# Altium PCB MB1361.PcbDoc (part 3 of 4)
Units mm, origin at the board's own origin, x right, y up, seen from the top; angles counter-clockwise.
Board outline 70 x 133.34 mm, 6 copper layers (Top Layer, Signal Layer 1, Signal Layer 2, Signal Layer 3, Signal Layer 4, Bottom Layer), stack 1.578 mm thick; 268 components, 251 nets, 1066 pads, 705 vias.
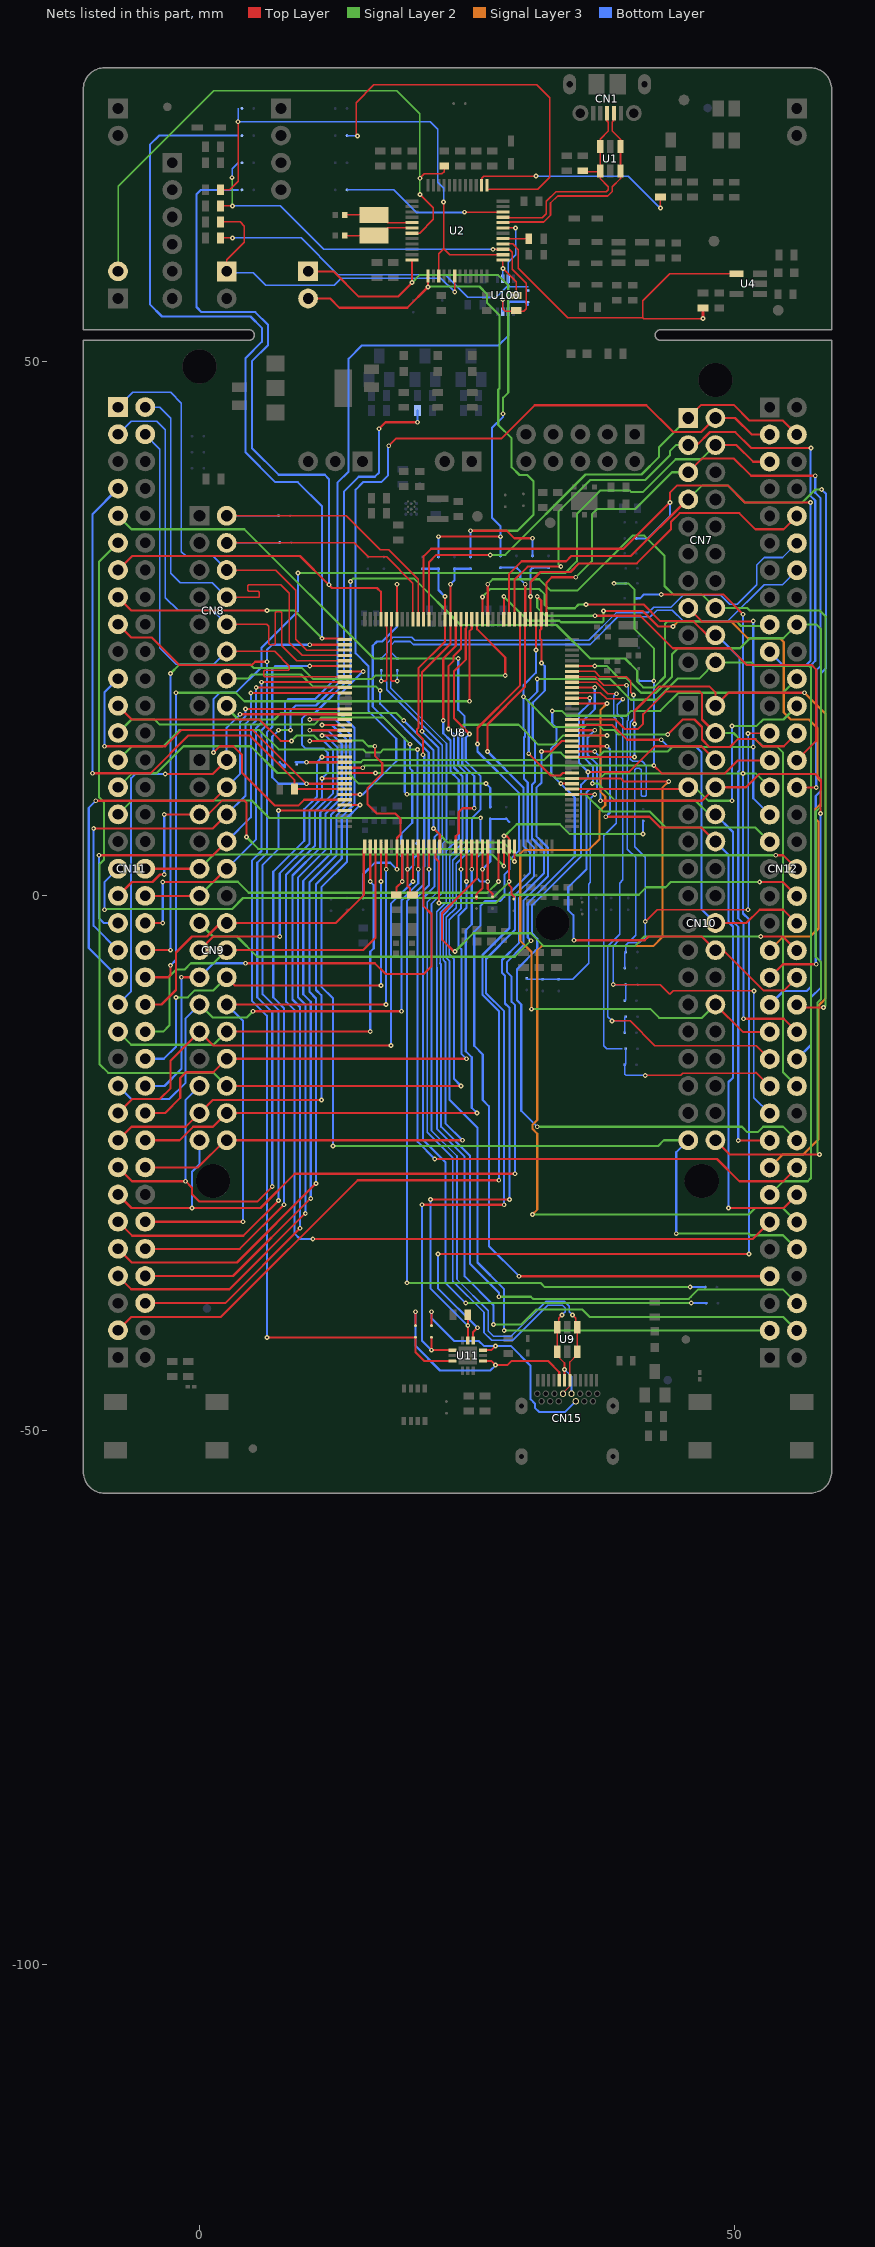
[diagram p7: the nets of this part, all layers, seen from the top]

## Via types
v1: diameter 0.45, hole 0.2, Top Layer to Bottom Layer, tented both sides, 705 vias

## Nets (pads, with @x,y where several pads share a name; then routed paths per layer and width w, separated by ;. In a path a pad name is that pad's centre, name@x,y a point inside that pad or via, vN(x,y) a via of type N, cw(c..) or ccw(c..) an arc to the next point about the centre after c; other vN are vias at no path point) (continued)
PA10: CN12.33 U8.102 | length 61.1
  Top Layer w0.2: U8.102@18.467,26.065 v1(18.467,29.147)
  Signal Layer 2 w0.2: v1(19.4,9.5) 36.1,9.5 37.7,7.9 42.1,7.9 43.605,6.395 52,6.395 CN12.33@53.34,5.055
  Bottom Layer w0.2: v1(18.467,29.147) 18.467,25.167 17.1,23.8 16.6,23.8 16.2,23.4 16.2,17.7 19.2,14.7 19.2,9.7 v1(19.4,9.5)
PA11: CN12.14 SB137.1 | length 43.4
  Bottom Layer w0.155: SB137.1@18.5,22.2 17.941,22.759 17.941,23.5 18.24,23.8 19.7,23.8 19.981,23.519 36.558,23.519 39.139,26.1 42.17,26.1 42.8,26.73 44.214,26.73 45.222,25.722 49.446,25.722 52.842,29.117 54.542,29.117 CN12.14@55.88,30.455
PA12: CN12.12 SB138.1 | length 45.9
  Bottom Layer w0.155: SB138.1@17,22.2 17.56,22.759 17.56,23.658 18.083,24.181 19.858,24.181 20.139,23.9 36.4,23.9 39,26.5 41.988,26.5 42.5,27.012 44.107,27.012 45.222,28.126 48.758,28.126 49.604,27.281 50.318,27.281 52.138,29.101 52.138,30.953 52.842,31.657 54.542,31.657 CN12.12@55.88,32.995
PA13: CN11.13 SB107.1 U8.105 | length 81.3
  Top Layer w0.2: CN11.13@-7.62,30.48 -6.305,31.795 9.405,31.795 v1(12.1,29.1) 12.4,28.8 16.61,28.8 16.967,28.443 U8.105@16.967,26.09
  Bottom Layer w0.2: 3.613,66.04 0.14,66.04 -0.279,65.621 -0.279,55.079 0.191,54.609 5.22,54.609 6.4,53.429 6.4,51.5 4.9,50 4.9,41.9 7.41,39.39 11.71,39.39 12.1,39 v1(12.1,29.1)
PA14: CN11.15 SB103.1 U8.109 | length 91.4
  Top Layer w0.2: CN11.15@-7.62,27.94 -6.38,26.7 v1(6.3,26.7) ; v1(11.465,24.09) U8.109@13.367,24.09
  Signal Layer 2 w0.2: v1(6.3,26.7) 8.855,26.7 v1(11.465,24.09)
  Bottom Layer w0.2: 3.613,71.12 -3.785,71.12 -4.648,70.256 -4.648,55.347 -3.502,54.2 4.763,54.2 5.831,53.132 5.831,51.831 4.3,50.3 4.3,41.5 7.1,38.7 9.2,38.7 11.465,36.435 v1(11.465,24.09)
PA15: CN11.17 SB10.1 U8.110 U11.3 | length 107.5
  Top Layer w0.2: CN11.17@-7.62,25.4 -6.395,24.175 -4.475,24.175 -1.9,21.6 4.9,21.6 5.2,21.9 v1(6.3,21.9) ; v1(6.3,-41.3) SB10.1@20.2,-41.3 20.2,-42.7 21,-43.5 U11.3@23.675,-43.5 ; v1(10.31,23.49) U8.110@13.392,23.49
  Bottom Layer w0.2: v1(6.3,-41.3) 6.3,-11.2 4.9,-9.8 4.9,3.3 5.8,4.2 5.8,15.5 6.3,16 v1(6.3,21.9) 6.3,23 6.79,23.49 v1(10.31,23.49)
PB0: SB160.1 SB161.1 SB162.2 U8.43 | length 24.4
  Top Layer w0.127: U8.43@35.067,9.49 v1(36.969,9.49)
  Bottom Layer w0.127: SB162.2@30.6,-7.7 30.7,-7.8 SB161.1@32.1,-7.8 SB160.1@33.6,-7.8 34.9,-7.8 36.4,-6.3 36.4,1.102 36.553,1.255 36.553,9.074 v1(36.969,9.49)
PB1: CN10.7 CN12.24 U8.44 | length 29.2
  Top Layer w0.2: U8.44@35.042,9.99 45.55,9.99 CN10.7@45.72,10.16
  Signal Layer 2 w0.2: CN10.7@45.72,10.16 46.34,10.16 47.6,8.9 v1(49.8,8.9) ; v1(49.8,15.9) 52.12,15.9 52.72,16.5 54.625,16.5 CN12.24@55.88,17.755
  Bottom Layer w0.2: v1(49.8,8.9) v1(49.8,15.9)
PB2: CN9.13 CN12.22 U8.45 | length 83.4
  Top Layer w0.2: v1(33.8,10.5) 35.057,10.5 U8.45@35.067,10.49
  Signal Layer 2 w0.2: CN9.13@0,-2.54 1.26,-3.8 3.5,-3.8 5.4,-5.7 29.5,-5.7 v1(31,-4.2) ; v1(33,17.3) 33.9,17.3 34.352,16.848 39.948,16.848 40.4,17.3 43.1,17.3 44.805,19.005 54.59,19.005 CN12.22@55.88,20.295
  Bottom Layer w0.2: v1(31,-4.2) 30.7,-3.9 30.7,-0.7 35.1,3.7 35.1,9.2 v1(33.8,10.5) 32.9,11.4 32.9,13.8 33.4,14.3 33.4,15.7 33.009,16.091 33,16.081 v1(33,17.3)
PB3: CN7.15 CN12.31 SB140.2 U8.132 | length 72.6
  Top Layer w0.2: v1(10,12.5) 13.382,12.5 U8.132@13.392,12.49 ; CN7.15@45.72,26.924 46.97,25.674 51.774,25.674 v1(51.8,25.7)
  Signal Layer 2 w0.2: v1(10,12.5) 15.08,12.5 15.28,12.7 32.2,12.7 32.9,13.4 33.8,13.4 34.3,12.9 37.2,12.9 37.8,13.5 43.8,13.5 44.225,13.925 v1(51.8,13.925)
  Bottom Layer w0.2: 8.99,12.49 9,12.5 v1(10,12.5) ; v1(51.8,25.7) v1(51.8,13.925) 51.8,9.135 CN12.31@53.34,7.595
PB4: CN12.27 SB134.1 SB139.1 U8.133 | length 62.8
  Top Layer w0.2: U8.133@13.392,11.99 v1(15.269,11.99) ; v1(42.5,12.2) 43.244,11.456 49.156,11.456 50.375,12.675 CN12.27@53.34,12.675
  Signal Layer 2 w0.2: v1(15.269,11.99) 15.479,12.2 v1(42.5,12.2) ; v1(38.767,29.236) 40.11,29.236 40.7,28.646 40.7,24.95 42.5,23.15 v1(42.5,20.1)
  Bottom Layer w0.127: CN12.27@53.34,12.675 CN12.27@53.34,12.725
  Bottom Layer w0.2: v1(38.767,29.236) SB134.1@39.867,29.236 ; SB139.1@41.1,20.1 v1(42.5,20.1) v1(42.5,12.2)
PB5: CN12.29 SB135.1 U8.134 U11.10 | length 150.7
  Top Layer w0.2: U8.134@13.392,11.49 U8.134@13.592,11.49 v1(16.474,11.49) ; v1(22.3,-33.5) v1(51.4,-33.5) ; U11.10@25.6,-41.575 25.6,-40.8 v1(26,-40.4) ; v1(43.2,28.2) 48.996,28.2 v1(50.848,26.348)
  Signal Layer 2 w0.2: v1(16.474,11.49) 32.81,11.49 33.31,10.99 37.485,10.99 37.951,11.456 v1(50.848,11.456) 52.019,11.456 CN12.29@53.34,10.135
  Bottom Layer w0.2: v1(22.3,-33.5) 22.3,-36.7 v1(26,-40.4) ; SB135.1@40.867,27.836 41.213,27.836 41.577,28.2 v1(43.2,28.2) ; v1(50.848,26.348) v1(50.848,11.456) 50.848,-1.648 51.4,-2.2 v1(51.4,-33.5)
PB6: CN9.15 CN12.17 U8.135 | length 99.2
  Top Layer w0.2: CN9.15@0,-5.08 1.28,-3.8 v1(7.5,-3.8) ; v1(11.465,10.99) U8.135@13.367,10.99
  Signal Layer 2 w0.2: v1(14.117,29.417) 14.4,29.7 20.05,29.7 24.41,25.34 33.4,25.34 36.54,22.2 39.8,22.2 40.95,21.05 40.95,20.05 41.5,19.5 42.539,19.5 43.552,20.513 43.552,25.452 43.774,25.674 50.226,25.674 50.652,25.248 53.34,25.248 CN12.17@53.34,25.375
  Bottom Layer w0.2: v1(7.5,-3.8) 7.5,2.1 10.3,4.9 10.3,8 11.465,9.165 v1(11.465,10.99) 12,11.525 12,13.4 11.6,13.8 9.9,13.8 9.6,14.1 9.6,16.6 10.1,17.1 10.8,17.1 14.117,20.417 v1(14.117,29.417)
PB7: CN11.21 R107.1 U8.136 | length 79.6
  Top Layer w0.2: v1(-8.89,14) -3.2,14 -1.7,15.5 4.99,15.5 v1(10,10.49) U8.136@13.392,10.49 ; v1(16.79,43.69) 17.4,44.3 v1(20.4,44.3)
  Signal Layer 2 w0.2: v1(7.4,15.5) v1(8.5,15.5)
  Bottom Layer w0.2: v1(-8.89,14) -8.89,19.05 CN11.21@-7.62,20.32 ; v1(7.4,15.5) 6.8,14.9 6.8,11.1 7.41,10.49 v1(10,10.49) ; v1(8.5,15.5) 8.5,17.3 9,17.8 10.9,17.8 13.5,20.4 13.5,37.8 14.9,39.2 16.4,39.2 16.79,39.59 v1(16.79,43.69) ; v1(20.4,44.3) R107.1@20.4,45.4
PB8: CN7.2 CN12.3 U8.138 | length 79.1
  Top Layer w0.2: U8.138@13.392,9.49 U8.138@13.592,9.49 v1(15,9.49) ; v1(17.7,42.1) 18.4,42.8 28.265,42.8 31.365,45.9 41.8,45.9 44.3,43.4 46.956,43.4 CN7.2@48.26,44.704 50.096,44.704 51.645,43.155 CN12.3@53.34,43.155
  Bottom Layer w0.2: v1(15,9.49) 15.294,9.49 18.4,12.596 18.4,14.7 15.8,17.3 15.8,21.5 14.6,22.7 14.6,38 15.3,38.7 17,38.7 17.648,39.348 17.648,42.048 v1(17.7,42.1)
PB9: CN7.4 CN12.5 U8.139 | length 89.2
  Top Layer w0.2: v1(1.3,13.4) 1.9,14 3.16,14 3.97,13.19 3.97,11.53 7.058,8.442 9.242,8.442 9.79,8.99 U8.139@13.367,8.99 ; CN7.4@48.26,42.164 50.236,42.164 51.785,40.615 CN12.5@53.34,40.615
  Signal Layer 2 w0.2: v1(9.2,30.2) 34.2,30.2 35.3,31.3 35.3,35.723 37.512,37.935 40.231,37.935 40.402,37.764 41.464,37.764 44.549,40.849 46.945,40.849 CN7.4@48.26,42.164
  Bottom Layer w0.2: v1(1.3,13.4) 1.3,18.405 1.9,19.005 3.405,19.005 5.8,21.4 5.8,23.2 9.2,26.6 v1(9.2,30.2)
PB10: CN12.25 SB151.1 SB157.2 U8.66 | length 70.5
  Top Layer w0.127: U8.66@35.042,20.99 36.969,20.99 37.459,20.5 39.9,20.5 40.347,20.053 40.347,19.053 v1(40.6,18.8) ; v1(41.7,-2.4) 42.8,-1.3 v1(51.3,-1.3) ; v1(51.3,15.2) 53.325,15.2 CN12.25@53.34,15.215
  Bottom Layer w0.127: SB157.2@39.775,-6.75 39.775,-5.35 SB151.1@39.875,-5.25 39.875,-4.625 40.1,-4.4 41.152,-4.4 41.7,-3.852 v1(41.7,-2.4) 41.7,3.6 40.7,4.6 40.7,11.8 40.846,11.946 41.154,11.946 41.3,11.8 41.3,9.4 41.4,9.3 41.7,9.3 41.8,9.4 41.8,12.19 41.416,12.575 40.518,12.575 40.292,12.8 40.275,12.8 40.275,16.262 40.6,16.588 v1(40.6,18.8) ; v1(51.3,-1.3) 51.316,-1.284 51.316,15.184 v1(51.3,15.2)
PB11: CN10.34 CN12.18 U8.67 | length 88.3
  Top Layer w0.2: U8.67@35.067,21.49 v1(36.969,21.49) ; CN10.34@48.26,-22.86 49.6,-24.2 v1(58,-24.2)
  Signal Layer 2 w0.2: v1(36.969,21.49) 36.991,21.512 38.088,21.512 39.2,20.4 39.9,20.4 41.3,19 42.7,19 44.2,20.5 44.2,22.6 44.759,23.159 50.559,23.159 51.5,24.1 54.605,24.1 CN12.18@55.88,25.375 57.725,25.375 58.152,24.948 58.152,8.391 57.648,7.887 57.648,-5.709 58.152,-6.213 58.152,-9.648 57.8,-10 57.8,-24 v1(58,-24.2)
PB13: CN7.5 CN12.30 U8.74 | length 68.1
  Top Layer w0.127: CN12.30@55.88,10.135 CN12.30@56.051,10.135
  Top Layer w0.2: U8.74@32.467,26.065 32.467,29.317 32.95,29.8 v1(35.2,29.8) ; CN7.5@45.72,39.624 46.996,40.9 50,40.9 51.6,39.3 v1(57.6,39.3) ; CN12.30@55.88,10.135 v1(57.7,10.135)
  Signal Layer 2 w0.2: v1(35.2,29.8) 36.7,31.3 36.7,35.7 37.193,36.193 40.77,36.193 44.201,39.624 CN7.5@45.72,39.624
  Bottom Layer w0.127: CN12.30@55.88,10.135 CN12.30@56.051,10.135
  Bottom Layer w0.2: v1(57.6,39.3) 57.6,37.7 58.1,37.2 58.1,21.5 57.7,21.1 v1(57.7,10.135)
PB14: CN12.28 R43.1 U8.75 U11.11 | length 121.6
  Top Layer w0.2: v1(21.6,-28.4) v1(29,-28.4) ; U11.11@25.1,-41.575 v1(25.1,-40.2) R43.1@25.1,-39.2 ; v1(31.6,28) 31.967,27.633 U8.75@31.967,26.09 ; U8.75@31.967,26.065 U8.75@31.967,25.865 31.967,24.967 31.848,24.848 31.848,24.052 32,23.9 v1(32,21.792) ; v1(37,26.2) 41.239,26.2 44.28,23.159 49.641,23.159 51.2,21.6 57.26,21.6 57.7,21.16 57.7,14.495 CN12.28@55.88,12.675
  Signal Layer 2 w0.2: v1(31.6,28) 31.6,26.967 32.367,26.2 v1(37,26.2)
  Bottom Layer w0.2: v1(21.6,-28.4) 21.6,-36.7 v1(25.1,-40.2) ; v1(29,-28.4) 29,-10.48 28.584,-10.064 28.584,-7.484 28.3,-7.2 28.3,-6 29.9,-4.4 29.9,-0.2 32.228,2.128 32.228,4.239 31.1,5.367 31.1,10.4 31.4,10.7 31.4,14.439 31.167,14.672 31.167,18.067 32.3,19.2 32.3,21.492 v1(32,21.792)
PB15: CN12.26 SB11.1 U8.76 U11.1 | length 114
  Top Layer w0.2: v1(20.8,-28.9) v1(28.5,-28.9) ; SB11.1@21.7,-41.3 v1(21.7,-42.5) U11.1@23.675,-42.5 ; v1(31.467,23) U8.76@31.467,25.865 U8.76@31.467,26.065 ; v1(43.8,15.1) 45.2,16.5 46.3,16.5 47,15.8 47,14.625 47.7,13.925 49.625,13.925 50.358,14.658 51.992,14.658 52.66,13.99 54.655,13.99 CN12.26@55.88,15.215
  Signal Layer 2 w0.2: v1@30.3,18.642 v1(30.321,18.621) 33.142,15.8 36,15.8 36.2,16 37.3,16 37.8,15.5 38.8,15.5 39.2,15.1 v1(43.8,15.1)
  Bottom Layer w0.2: v1(20.8,-28.9) 20.8,-41.6 v1(21.7,-42.5) ; v1(28.5,-28.9) 28.5,-10.809 26.8,-9.109 26.8,-5.9 29.5,-3.2 29.5,0.05 31.3,1.85 31.3,4.5 30.7,5.1 30.7,10.6 30.348,10.952 30.348,14.809 30.452,14.913 30.452,15.5 30.321,15.631 v1(30.321,18.621) 30.321,19.721 31.467,20.867 v1(31.467,23)
PC0: CN9.11 CN11.38 U8.26 | length 37.5
  Top Layer w0.2: CN11.38@-5.08,0 CN9.11@0,0 ; v1(27.967,1.333) U8.26@27.967,4.415
  Signal Layer 2 w0.2: CN9.11@0,0 1.315,1.315 3.585,1.315 4.604,0.296 26.93,0.296 v1(27.967,1.333)
PC1: CN9.9 CN11.36 U8.27 | length 36.1
  Top Layer w0.2: CN11.36@-5.08,2.54 CN9.9@0,2.54 ; v1(28.467,2.8) U8.27@28.467,4.39
  Signal Layer 2 w0.2: CN9.9@0,2.54 1.315,3.855 27.412,3.855 v1(28.467,2.8)
PC2: CN11.35 SB8.1 SB144.1 U8.28 | length 64.6
  Top Layer w0.2: v1(28.483,5.6) 28.711,5.6 28.967,5.344 U8.28@28.967,4.615 v1(28.967,1.333) 28.967,1.006 29.2,0.773 29.2,0.151 29.451,-0.1
  Signal Layer 2 w0.2: v1(-8.9,-1.3) -8.825,-1.225 3.047,-1.225 4.072,-0.2 27.434,-0.2 v1(28.967,1.333) ; v1(28.483,5.6) 28.567,5.6 29.667,6.7 33.7,6.7 34.6,5.8 v1(41.5,5.8)
  Bottom Layer w0.2: v1(-8.9,-1.3) -8.9,1.26 CN11.35@-7.62,2.54 ; v1(41.5,5.8) SB144.1@41.5,7
PC3: CN9.5 CN11.37 U8.29 | length 49.5
  Top Layer w0.2: CN11.37@-7.62,0 -6.32,1.3 -4.4,1.3 -3.7,2 v1(-3.3,2) ; v1(-3.3,7.62) CN9.5@0,7.62 0.808,7.62 2.123,8.935 4.165,8.935 4.4,8.7 v1(4.4,5.5) ; v1(29.467,3.2) U8.29@29.467,4.39
  Signal Layer 2 w0.2: v1(4.4,5.5) 5.5,4.4 28.267,4.4 v1(29.467,3.2)
  Bottom Layer w0.2: v1(-3.3,2) v1(-3.3,7.62)
PC6: CN7.1 CN12.4 U8.96 | length 47.3
  Top Layer w0.2: U8.96@21.467,26.065 21.467,31.217 22.15,31.9 v1(27.2,31.9) ; CN7.1@45.72,44.704 46.945,45.929 49.971,45.929 51.43,44.47 54.565,44.47 CN12.4@55.88,43.155
  Signal Layer 2 w0.2: v1(27.2,31.9) 28.6,31.9 36.115,39.415 41.353,39.415 43,41.062 43,41.984 CN7.1@45.72,44.704
PC7: CN12.19 SB118.1 U8.97 | length 70.4
  Top Layer w0.2: U8.97@20.967,26.09 20.967,31.767 21.667,32.467 39.667,32.467 v1(44,36.8) 44,37.71 44.689,38.399 46.227,38.399 46.228,38.4 47.752,38.4 47.753,38.399 49.401,38.399 51,36.8 v1(57.15,36.8)
  Bottom Layer w0.2: SB118.1@40.867,33.436 41.936,33.436 44,35.5 v1(44,36.8) ; CN12.19@53.34,22.835 54.575,21.6 56.76,21.6 57.15,21.99 v1(57.15,36.8)
PC8: CN8.2 SB119.2 U8.98 | length 28.8
  Top Layer w0.127: CN8.2@2.54,35.56 13.74,35.56 16.925,32.375 17.725,32.375 20.467,29.633 U8.98@20.467,26.065
  Bottom Layer w0.127: CN8.2@2.54,35.56 SB119.2@7.4,35.56
PC9: CN8.4 SB122.1 U8.99 | length 27.2
  Top Layer w0.127: CN8.4@2.54,33.02 14.48,33.02 15.8,31.7 17.518,31.7 19.967,29.251 U8.99@19.967,26.065
  Bottom Layer w0.127: CN8.4@2.54,33.02 7.46,33.02 SB122.1@7.5,33.06
PC10: CN8.6 CN11.1 U8.111 | length 42.4
  Top Layer w0.127: CN8.6@2.54,30.48 7.12,30.48 9,28.6 9,24.02 10.03,22.99 U8.111@13.392,22.99
  Bottom Layer w0.127: CN11.1@-7.62,45.72 -6.24,47.1 -2.7,47.1 -1.7,46.1 -1.7,32.2 -1.3,31.8 1.22,31.8 CN8.6@2.54,30.48
PC11: CN8.8 CN11.2 U8.112 | length 42.9
  Top Layer w0.127: CN8.8@2.54,27.94 5.54,27.94 5.6,28 5.6,28.4 5.5,28.5 4.6,28.5 4.5,28.6 4.5,29 4.6,29.1 7.6,29.1 8.4,28.3 8.4,23.7 9.61,22.49 U8.112@13.392,22.49
  Bottom Layer w0.127: CN11.2@-5.08,45.72 -3.72,45.72 -2.7,44.7 -2.7,30.2 -1.78,29.28 1.2,29.28 CN8.8@2.54,27.94
PC12: CN8.10 CN11.3 U8.113 | length 47
  Top Layer w0.127: CN8.10@2.54,25.4 6.3,25.4 6.5,25.2 6.5,23.6 6.6,23.5 7,23.5 7.1,23.6 7.1,26.5 7.2,26.6 7.6,26.6 7.7,26.5 7.7,23.4 9.11,21.99 U8.113@13.392,21.99
  Bottom Layer w0.127: CN11.3@-7.62,43.18 -6.4,44.4 -4.01,44.4 -3.2,43.59 -3.2,27.9 -2,26.7 1.24,26.7 CN8.10@2.54,25.4
PC13: CN11.23 SB154.2 U8.7 | length 46.9
  Top Layer w0.2: CN11.23@-7.62,17.78 -6.34,16.5 5.6,16.5 7.6,14.5 v1(8.6,14.5) ; v1(16.4,14) 16.4,13.1 17.1,12.4 17.1,11.477 15.7,10.077 15.7,8.587 16.587,7.7 18.3,7.7 18.8,7.2 18.8,5.75 18.467,5.417 U8.7@18.467,4.615 U8.7@18.467,4.415 ; v1(18.467,2.488) U8.7@18.467,4.39
  Signal Layer 2 w0.2: v1(8.6,14.5) 9.1,15 10.7,15 11.162,14.538 15.262,14.538 15.8,14 v1(16.4,14)
  Bottom Layer w0.2: SB154.2@15.3,-0.2 15.3,2 16.4,3.1 17.855,3.1 v1(18.467,2.488)
PC14: CN11.25 SB148.2 | length 39.2
  Signal Layer 2 w0.2: CN11.25@-7.62,15.24 -6.36,16.5 -4.2,16.5 -3.72,16.02 10.72,16.02 11.4,16.7 17.19,16.7 v1(19.7,14.19)
  Bottom Layer w0.2: SB148.2@18.867,4.9 18.867,5.8 19.9,6.833 19.9,11.7 19.7,11.9 v1(19.7,14.19)
PC14-OSC32_IN: R34.1 SB148.1 U8.8 | length 7.1
  Top Layer w0.2: R34.1@18.417,0.096 18.417,0.783 v1(18.967,1.333) U8.8@18.967,4.415
  Bottom Layer w0.2: SB148.1@18.867,3.8 18.967,3.7 v1(18.967,1.333)
PC15: CN11.27 SB147.2 | length 39
  Signal Layer 2 w0.2: CN11.27@-7.62,12.7 -6.32,14 -3.4,14 -1.9,15.5 5.6,15.5 7.4,13.7 15.3,13.7 15.6,13.4 16.9,13.4 17.2,13.7 v1(20.4,13.7)
  Bottom Layer w0.2: SB147.2@20.3,4.9 20.4,5 v1(20.4,13.7)
PC15-OSC32_OUT: R35.1 SB147.1 U8.9 | length 6.2
  Top Layer w0.2: U8.9@19.467,4.39 v1(19.467,2.488) 19.467,0.923 19.7,0.69 19.7,0.305 R35.1@19.916,0.089
  Bottom Layer w0.2: v1(19.467,2.488) 19.623,2.488 20,2.865 20,3.5 SB147.1@20.3,3.8
PD0: CN9.25 CN11.57 U8.114 | length 82.4
  Top Layer w0.2: CN11.57@-7.62,-25.4 -6.32,-26.7 v1(-1.3,-26.7) -0.7,-27.3 -0.7,-27.9 0,-28.6 5.4,-28.6 v1(6.8,-27.2) ; v1(10.31,21.49) U8.114@13.392,21.49
  Bottom Layer w0.2: v1(-1.3,-26.7) -1.3,-19.08 CN9.25@0,-17.78 ; v1(6.8,-27.2) 6.8,-10.9 5.4,-9.5 5.4,3.1 6.3,4 6.3,15.3 6.8,15.8 6.8,21.2 7.09,21.49 v1(10.31,21.49)
PD1: CN9.27 CN11.55 U8.115 | length 65.9
  Top Layer w0.2: CN11.55@-7.62,-22.86 -6.36,-21.6 -1.28,-21.6 CN9.27@0,-20.32 1.225,-19.095 v1(11.4,-19.095) ; U8.115@13.417,20.99 v1(15.319,20.99)
  Bottom Layer w0.2: v1(11.4,-19.095) 11.4,-9.3 10.9,-8.8 10.9,1.1 13.3,3.5 13.3,7.4 14.5,8.6 14.5,15.7 13,17.2 13,18.706 15.284,20.99 v1(15.319,20.99)
PD2: CN8.12 CN11.4 U8.116 | length 45
  Top Layer w0.127: CN8.12@2.54,22.86 7.04,22.86 8.4,21.5 8.4,21.2 8.3,21.1 6.1,21.1 6,21 6,20.6 6.11,20.49 U8.116@13.392,20.49
  Bottom Layer w0.127: CN11.4@-5.08,43.18 -3.7,41.8 -3.7,23.2 -2.16,21.66 1.34,21.66 CN8.12@2.54,22.86
PD3: CN9.10 CN11.40 U8.117 | length 38.3
  Top Layer w0.2: CN11.40@-5.08,-2.54 v1(-3.44,-2.54) ; v1(-3.44,1.3) 1.3,1.3 CN9.10@2.54,2.54 ; v1(5.8,19.99) U8.117@13.367,19.99
  Bottom Layer w0.2: v1(-3.44,-2.54) v1(-3.44,1.3) ; CN9.10@2.54,2.54 5.3,5.3 5.3,15.7 5.8,16.2 v1(5.8,19.99)
PD4: CN9.8 CN11.39 U8.118 | length 44
  Top Layer w0.2: v1(-9.4,3.8) 1.26,3.8 CN9.8@2.54,5.08 ; v1(5.3,19.49) U8.118@13.392,19.49
  Bottom Layer w0.2: v1(-9.4,3.8) -9.4,-2.1 -8.96,-2.54 CN11.39@-7.62,-2.54 ; CN9.8@2.54,5.08 4.8,7.34 4.8,15.9 5.3,16.4 v1(5.3,19.49)
PD5: CN9.6 CN11.41 U8.119 | length 46.2
  Top Layer w0.2: v1(-9.9,6.305) 1.225,6.305 CN9.6@2.54,7.62 ; v1(4.8,18.99) U8.119@13.367,18.99
  Bottom Layer w0.2: v1(-9.9,6.305) -9.9,-2.8 CN11.41@-7.62,-5.08 ; CN9.6@2.54,7.62 4.31,9.39 4.31,16.11 4.8,16.6 v1(4.8,18.99)
PD6: CN9.4 CN11.43 U8.122 | length 47.8
  Top Layer w0.2: v1(-9.7,8.9) 1.28,8.9 CN9.4@2.54,10.16 ; v1(4.3,17.49) U8.122@13.392,17.49
  Bottom Layer w0.2: v1(-9.7,8.9) -10.366,8.234 -10.366,-4.874 CN11.43@-7.62,-7.62 ; CN9.4@2.54,10.16 3.8,11.42 3.8,16.3 4.3,16.8 v1(4.3,17.49)
PD7: CN9.2 CN11.45 U8.123 | length 45.7
  Top Layer w0.2: v1(-3.2,11.4) 1.24,11.4 CN9.2@2.54,12.7 ; v1(3.8,16.99) U8.123@13.367,16.99
  Bottom Layer w0.2: CN11.45@-7.62,-10.16 -6.395,-8.935 -6.395,11.005 -6,11.4 v1(-3.2,11.4) ; CN9.2@2.54,12.7 2.54,15.73 v1(3.8,16.99)
PD8: CN12.10 SB123.1 SB124.1 U8.77 | length 36.7
  Top Layer w0.2: U8.77@30.967,26.09 v1(30.967,27.992) 30.967,29.367 31.9,30.3 34.7,30.3 35.5,31.1 40.9,31.1 44.1,34.3 44.1,34.985 44.915,35.8 50.5,35.8 52,34.3 54.645,34.3 CN12.10@55.88,35.535
  Bottom Layer w0.2: v1(30.967,27.992) 30.967,30.517 SB124.1@31.15,30.7 SB123.1@32.65,30.7
PD9: CN11.69 SB125.1 SB126.1 U8.78 | length 106.2
  Top Layer w0.2: CN11.69@-7.62,-40.64 -6.38,-39.4 2,-39.4 14.8,-26.6 v1(28,-26.6) ; v1(26.936,13.5) 26.936,16.036 30.448,19.548 30.448,26.046 30.467,26.065 v1(30.467,29.147)
  Bottom Layer w0.2: v1(26.936,13.5) 30.3,10.136 30.3,4.7 30.919,4.081 30.919,2.163 29,0.244 29,-3.008 26.473,-5.535 26.473,-9.244 28,-10.771 v1(28,-26.6) ; SB126.1@28.15,30.7 SB125.1@29.65,30.7 30,30.35 30,29.614 v1(30.467,29.147)
PD10: CN12.65 U8.79 | length 92.6
  Top Layer w0.2: v1(26,14.2) 26,15.7 29.967,19.667 U8.79@29.967,25.865 U8.79@29.967,26.065 ; v1(29.9,-35.585) CN12.65@53.34,-35.585
  Bottom Layer w0.2: v1(26,14.2) 26,13.5 29.9,9.6 29.9,4.272 29.015,3.387 29.015,2.49 28.515,1.99 28.515,-0.085 28.114,-0.486 26.724,-0.486 26.3,-0.91 26.3,-2.75 25.7,-3.35 25.7,-14.036 26.5,-14.836 26.5,-19.1 27.069,-19.669 27.069,-32.754 v1(29.9,-35.585)
PD11: CN7.3 CN12.45 U8.80 | length 96.5
  Top Layer w0.2: U8.80@29.467,26.065 29.467,29.567 30.7,30.8 v1(33.8,30.8) ; CN7.3@45.72,42.164 46.528,42.164 47.753,43.389 49.476,43.389 49.485,43.38 50.12,43.38 51.6,41.9 v1(57.2,41.9)
  Signal Layer 2 w0.2: v1(33.8,30.8) 33.569,31.031 33.569,35.919 36.55,38.9 41.7,38.9 44,41.2 44,41.6 44.564,42.164 CN7.3@45.72,42.164
  Bottom Layer w0.2: CN12.45@53.34,-10.185 54.625,-8.9 56.8,-8.9 57.2,-8.5 57.2,21.578 57.602,21.98 57.602,36.987 57.148,37.441 57.148,41.848 v1(57.2,41.9)
PD12: CN7.7 CN12.43 U8.81 | length 87.7
  Top Layer w0.2: U8.81@28.967,26.09 28.967,30.117 30.15,31.3 34.3,31.3 34.8,31.8 40.361,31.8 45.645,37.084 CN7.7@45.72,37.084 ; CN12.43@53.34,-7.645 54.585,-6.4 v1(57.7,-6.4)
  Signal Layer 2 w0.2: CN7.7@45.72,37.084 47.035,38.399 49.401,38.399 51,36.8 56.378,36.8 57.578,38 v1(58.2,38)
  Bottom Layer w0.2: v1(57.7,-6.4) 57.648,-6.348 57.648,9.348 58.152,9.852 58.152,20.852 58.6,21.3 58.6,37.6 v1(58.2,38)
PD13: CN12.41 U8.82 | length 66.7
  Top Layer w0.2: U8.82@28.467,26.065 v1(28.467,28) ; v1(37.8,26.652) 41.448,26.652 42.9,25.2 v1(44.3,25.2)
  Signal Layer 2 w0.2: v1(28.467,28) 30.727,25.74 33.66,25.74 33.8,25.6 37.7,25.6 37.8,25.7 v1(37.8,26.652)
  Signal Layer 3 w0.2: v1(44.3,25.2) 44.774,25.674 49.726,25.674 51.3,24.1 54.3,24.1 54.655,23.745 54.655,17.145 55.3,16.5 57,16.5 57.8,15.7 57.8,11 58.152,10.648 58.152,8.652 57.648,8.148 57.648,7.2 57.9,6.948 57.9,-3.048 57.158,-3.79 54.655,-3.79 CN12.41@53.34,-5.105
PD14: CN7.16 CN12.46 U8.85 | length 81.5
  Top Layer w0.2: U8.85@26.967,26.065 v1(26.967,29.147) ; CN12.46@55.88,-10.185 56.142,-10.447 v1(58.358,-10.447)
  Signal Layer 2 w0.2: v1(26.967,29.147) 27.434,29.614 31.786,29.614 32.848,28.552 35.352,28.552 40.5,33.7 41.6,33.7 43.5,31.8 43.5,28.99 44.29,28.2 46.984,28.2 CN7.16@48.26,26.924 51.224,26.924 51.458,26.69 58.01,26.69 58.6,26.1 58.552,26.052 58.552,-10.253 v1(58.358,-10.447)
PD15: CN7.18 CN12.48 U8.86 | length 69.3
  Top Layer w0.2: U8.86@26.467,26.065 v1(26.467,27.967) ; v1(36.152,27.248) 41.552,27.248 43.101,25.699 46.201,25.699 47.516,24.384 CN7.18@48.26,24.384 ; v1(50.9,-11.5) 54.655,-11.5 CN12.48@55.88,-12.725
  Signal Layer 2 w0.2: v1(26.467,27.967) 27.195,28.695 31.805,28.695 32.3,28.2 32.3,27.215 32.615,26.9 35.1,26.9 35.448,27.248 v1(36.152,27.248)
  Bottom Layer w0.2: CN7.18@48.26,24.384 48.416,24.384 50.5,22.3 50.5,11.747 50.396,11.643 50.396,-2.096 50.9,-2.6 v1(50.9,-11.5)
PE0: CN10.33 CN12.64 U8.140 | length 90
  Top Layer w0.2: U8.140@13.392,8.49 U8.140@13.592,8.49 v1(15,8.49)
  Signal Layer 2 w0.2: v1(12.5,-23.4) 42.9,-23.4 43.44,-22.86 CN10.33@45.72,-22.86 ; v1(44.6,-31.6) 51.4,-31.6 51.545,-31.745 54.58,-31.745 CN12.64@55.88,-33.045
  Bottom Layer w0.2: v1(12.5,-23.4) 12.5,-9.6 11.4,-8.5 11.4,0.8 13.8,3.2 13.8,7.29 v1(15,8.49) ; v1(44.6,-31.6) 44.6,-23.98 CN10.33@45.72,-22.86
PE1: CN11.61 U8.141 | length 60.7
  Top Layer w0.2: CN11.61@-7.62,-30.48 -6.305,-31.795 4.105,-31.795 v1(7.4,-28.5) ; v1(7.4,7.99) U8.141@13.392,7.99
  Bottom Layer w0.2: v1(7.4,-28.5) 7.4,-10.7 5.9,-9.2 5.9,2.9 7.4,4.4 v1(7.4,7.99)
PE2: CN9.14 CN11.46 U8.1 | length 31.1
  Top Layer w0.2: CN11.46@-5.08,-10.16 -3.56,-10.16 -2.2,-8.8 -2.2,-5.3 -0.7,-3.8 0.7,-3.8 1.96,-2.54 CN9.14@2.54,-2.54 12.76,-2.54 15.367,0.067 U8.1@15.367,4.39
PE3: CN9.22 CN11.47 U8.2 | length 42
  Top Layer w0.2: CN9.22@2.54,-12.7 v1(15.967,-12.7) ; v1(15.967,1.333) U8.2@15.967,4.415
  Signal Layer 2 w0.2: CN11.47@-7.62,-12.7 -6.395,-13.925 1.315,-13.925 CN9.22@2.54,-12.7
  Bottom Layer w0.2: v1(15.967,-12.7) 15.967,-5.233 16.3,-4.9 16.3,1 v1(15.967,1.333)
PE4: CN9.16 CN11.48 U8.3 | length 36.2
  Top Layer w0.2: CN9.16@2.54,-5.08 15.3,-5.08 16.467,-3.913 U8.3@16.467,4.39
  Signal Layer 2 w0.2: CN11.48@-5.08,-12.7 -3.4,-12.7 -2.8,-12.1 -2.8,-7.5 -2.2,-6.9 -1.4,-6.9 -0.805,-6.305 1.315,-6.305 CN9.16@2.54,-5.08
PE5: CN9.18 CN11.50 U8.4 | length 41
  Top Layer w0.2: CN9.18@2.54,-7.62 3.32,-8.4 v1(16.967,-8.4) ; v1(16.967,1.333) U8.4@16.967,4.415
  Signal Layer 2 w0.2: v1(-2.2,-9.5) -1.1,-9.5 -0.445,-8.845 1.315,-8.845 CN9.18@2.54,-7.62
  Bottom Layer w0.2: CN11.50@-5.08,-15.24 -3.34,-15.24 -2.2,-14.1 v1(-2.2,-9.5) ; v1(16.967,-8.4) v1(16.967,1.333)
PE6: CN9.20 CN11.62 U8.5 | length 59.6
  Top Layer w0.2: CN11.62@-5.08,-30.48 v1(4.08,-30.48) ; CN9.20@2.54,-10.16 v1(17.448,-10.16) ; v1(17.467,2.488) U8.5@17.467,4.39
  Bottom Layer w0.2: CN9.20@2.54,-10.16 4.08,-11.7 v1(4.08,-30.48) ; v1(17.448,-10.16) 17.448,2.469 v1(17.467,2.488)
PE7: CN10.20 CN12.44 U8.55 | length 47.5
  Top Layer w0.2: v1(35.032,-4.152) 41.652,-4.152 42.004,-3.8 46.98,-3.8 CN10.20@48.26,-5.08 48.98,-5.08 52.77,-8.87 54.655,-8.87 CN12.44@55.88,-7.645 ; U8.55@35.067,15.49 v1(36.969,15.49)
  Bottom Layer w0.2: v1(35.032,-4.152) 34.973,-4.093 34.973,-1.806 34.5,-1.333 34.5,0.8 36.2,2.5 36.2,9.7 36.49,9.99 37.09,9.99 37.198,10.098 37.198,12.302 36.3,13.2 36.3,14.821 v1(36.969,15.49)
PE8: CN10.18 CN12.40 U8.56 | length 38.2
  Top Layer w0.2: U8.56@35.042,15.99 38.61,15.99 40,14.6 v1(43.2,14.6) ; CN10.18@48.26,-2.54 51.16,-2.54 52.4,-1.3 54.615,-1.3 CN12.40@55.88,-2.565
  Bottom Layer w0.2: v1(43.2,14.6) 43.8,14 46.4,14 46.945,13.455 46.945,-1.225 CN10.18@48.26,-2.54
PE9: CN10.4 CN12.52 U8.57 | length 57.4
  Top Layer w0.2: U8.57@35.067,16.49 38.91,16.49 39.8,15.6 41,15.6 41.5,16.1 41.5,17 43.6,19.1 46.8,19.1 47,18.9 47,16.5 CN10.4@48.26,15.24
  Signal Layer 2 w0.2: CN10.4@48.26,15.24 49.96,15.24 50.542,14.658 51.992,14.658 52.66,13.99 54.01,13.99 54.6,13.4 54.6,-16.525 CN12.52@55.88,-17.805
PE10: CN10.24 CN12.47 U8.60 | length 63.6
  Top Layer w0.2: U8.60@35.042,17.99 v1(38.124,17.99) ; CN10.24@48.26,-10.16 50.825,-12.725 CN12.47@53.34,-12.725
  Signal Layer 2 w0.2: v1(31.052,-10.6) 42.2,-10.6 43.01,-11.41 47.01,-11.41 CN10.24@48.26,-10.16
  Signal Layer 3 w0.2: v1(31.052,-10.6) 31.052,-5.252 30,-4.2 30,3.933 30.367,4.3 36.41,4.3 37.421,5.311 37.421,7.942 37.952,8.473 37.952,9.3 37.5,9.752 37.5,17.366 v1(38.124,17.99)
PE11: CN10.6 CN12.56 U8.61 | length 84.9
  Top Layer w0.2: U8.61@35.067,18.49 35.077,18.5 v1(36.5,18.5) ; v1(36.341,11.6) 40.2,11.6 42.6,14 46.96,14 CN10.6@48.26,12.7
  Signal Layer 2 w0.2: v1(31.6,-21.6) 50.748,-21.6 51.248,-22.1 52.22,-22.1 52.72,-21.6 54.595,-21.6 CN12.56@55.88,-22.885
  Bottom Layer w0.2: v1(31.6,-21.6) 30.1,-20.1 30.1,-10.161 29.7,-9.761 29.7,-6.85 31.6,-4.95 31.6,-4 31.12,-3.52 31.12,-0.88 35.7,3.7 35.7,10.4 36.341,11.041 v1(36.341,11.6) 35.5,12.441 35.5,17.021 36.5,18.021 v1(36.5,18.5)
PE12: CN12.49 SB163.1 SB164.2 U8.62 | length 55
  Top Layer w0.127: U8.62@35.042,18.99 37.51,18.99 38.083,18.417 39.583,18.417 v1(39.6,18.4) ; v1(38.6,-11.7) 40.3,-11.7 42.6,-14 52.075,-14 CN12.49@53.34,-15.265
  Bottom Layer w0.127: v1(39.6,18.4) 39.1,17.9 39.1,17.048 39.6,16.548 39.6,1.5 39.3,1.2 39.3,-3.6 38.2,-4.7 38.2,-11.3 v1(38.6,-11.7) 39.775,-11.7 ; SB164.2@39.775,-12.8 39.775,-11.7 ; 39.8,-11.7 39.775,-11.7 ; SB163.1@39.875,-11.3 39.775,-11.4 39.775,-11.7
PE13: CN10.10 CN12.55 U8.63 | length 58.9
  Top Layer w0.2: U8.63@35.067,19.49 v1(36.969,19.49) ; v1(50.4,-22.885) CN12.55@53.34,-22.885
  Signal Layer 2 w0.2: v1(36.746,10.5) 37.3,10.5 38.9,8.9 46.4,8.9 47.68,7.62 CN10.10@48.26,7.62
  Bottom Layer w0.2: v1(36.746,10.5) 36.8,10.554 36.8,12.1 35.9,13 35.9,16.4 36.969,17.469 v1(36.969,19.49) v1@36.851,19.49 ; CN10.10@48.26,7.62 49.9,5.98 49.9,-2.4 50.4,-2.9 v1(50.4,-22.885)
PE14: CN12.51 SB165.1 SB166.2 U8.64 | length 56.5
  Top Layer w0.127: U8.64@35.042,19.99 37.11,19.99 38.2,18.9 v1(39,18.9) ; v1(41.7,-16.8) 45.019,-16.8 45.228,-16.592 51.943,-16.592 52.035,-16.5 CN12.51@53.34,-17.805
  Bottom Layer w0.127: v1(39,18.9) 38.767,18.667 38.767,16.733 39,16.5 39,6.8 37.8,5.6 37.8,0.587 37.798,0.586 37.798,-14 38.098,-14.3 39.525,-14.3 ; SB165.1@39.875,-14.3 39.875,-15.7 SB166.2@39.775,-15.8 39.775,-16.675 39.9,-16.8 v1(41.7,-16.8)
PE15: CN12.53 SB158.1 SB159.2 U8.65 | length 63.6
  Top Layer w0.127: U8.65@35.042,20.49 37.01,20.49 37.8,19.7 v1(39.932,19.7) ; v1(38.7,-8.3) 43.1,-8.3 44,-9.2 44.3,-8.9 v1(51.86,-8.9)
  Bottom Layer w0.127: SB159.2@39.775,-9.8 39.875,-9.7 SB158.1@39.875,-8.3 v1(38.7,-8.3) 38.7,-4.7 39.285,-4.115 40.385,-4.115 40.802,-3.698 40.802,0.586 40.8,0.588 40.8,3.6 40.021,4.379 40.021,16.367 40.1,16.447 40.1,19.532 v1(39.932,19.7) ; v1(51.86,-8.9) 51.86,-18.865 CN12.53@53.34,-20.345
PF0: CN9.21 CN11.53 U8.10 | length 50
  Top Layer w0.2: CN11.53@-7.62,-20.32 -6.305,-19.005 -3.705,-19.005 -2.7,-18 -2.7,-15.4 CN9.21@0,-12.7 1.315,-14.015 1.33,-14 v1(17.9,-14) ; v1(19.967,1.333) U8.10@19.967,4.415
  Bottom Layer w0.2: v1(17.9,-14) 17.9,-0.734 v1(19.967,1.333)
PF1: CN9.19 CN11.51 U8.11 | length 50.8
  Top Layer w0.2: v1(5,-10.8) v1(18.9,-10.8) ; v1(20.467,2.488) U8.11@20.467,4.39
  Signal Layer 2 w0.2: CN9.19@0,-10.16 1.225,-11.385 4.415,-11.385 v1(5,-10.8)
  Bottom Layer w0.2: CN11.51@-7.62,-17.78 -6.395,-19.005 -2.835,-19.005 -1.3,-17.47 -1.3,-11.46 CN9.19@0,-10.16 ; v1(18.9,-10.8) 18.9,-0.4 20.467,1.167 v1(20.467,2.488)
PF2: CN9.17 CN11.52 U8.12 | length 48.6
  Top Layer w0.2: v1(-1.7,-7.62) CN9.17@0,-7.62 ; v1(4.3,-6.3) 16.4,-6.3 17.4,-7.3 21,-7.3 21.7,-6.6 21.7,-1.7 20.967,-0.967 U8.12@20.967,4.415
  Bottom Layer w0.2: CN11.52@-5.08,-17.78 -3.28,-17.78 -1.7,-16.2 v1(-1.7,-7.62) ; CN9.17@0,-7.62 1.315,-6.305 4.295,-6.305 v1(4.3,-6.3)
PF3: CN8.14 CN12.58 U8.13 | length 99.1
  Top Layer w0.2: v1(21.467,2.488) U8.13@21.467,4.39 ; v1(22,-24.615) 48.415,-24.615 50.5,-26.7 54.605,-26.7 CN12.58@55.88,-25.425
  Signal Layer 2 w0.2: CN8.14@2.54,20.32 4.52,20.32 4.9,20.7 9.5,20.7 10.6,19.6 16.5,19.6 v1(16.9,19.2)
  Bottom Layer w0.2: v1(16.9,19.2) 16.9,17.961 21.448,13.413 21.448,2.507 v1(21.467,2.488) 21.467,0.976 20.4,-0.091 20.4,-23.015 v1(22,-24.615)
PF4: CN12.38 U8.14 | length 40.1
  Top Layer w0.2: U8.14@21.967,4.415 22.09,4.292 22.09,3.496 22.4,3.186 v1(22.4,-0.667) ; v1(52.4,1.29) 54.565,1.29 CN12.38@55.88,-0.025
  Signal Layer 2 w0.2: v1(22.4,-0.667) 27.718,-0.667 28.485,0.1 41.1,0.1 41.8,0.8 43.6,0.8 44.09,1.29 v1(52.4,1.29)
PF5: CN8.16 CN12.36 U8.15 | length 66.7
  Top Layer w0.2: v1(21.9,6.3) 22.467,5.733 U8.15@22.467,4.615 U8.15@22.467,4.415 ; U8.15@22.454,4.402 U8.15@22.467,4.39 ; v1(53.9,3.8) 54.595,3.8 CN12.36@55.88,2.515
  Signal Layer 2 w0.2: CN8.16@2.54,17.78 2.54,17.611 3.651,16.5 7.01,16.5 7.61,17.1 18.4,17.1 v1(19.1,16.4) ; v1(21.9,6.3) 23.2,5 28.4,5 29.6,3.8 v1(53.9,3.8)
  Bottom Layer w0.2: v1(19.1,16.4) 21.9,13.6 v1(21.9,6.3)
PF6: CN11.9 U8.18 | length 57.3
  Top Layer w0.2: U8.18@23.967,4.415 U8.18@23.967,4.615 23.967,5.574 24.248,5.855 24.248,7.848 24.6,8.2 v1(25.7,8.2)
  Signal Layer 2 w0.2: CN11.9@-7.62,35.56 -6.36,34.3 4.2,34.3 16.3,22.2 v1(24.2,22.2)
  Bottom Layer w0.2: v1(24.2,22.2) 24.2,17.4 24.8,16.8 24.8,15.3 24.573,15.073 24.573,12.317 25.7,11.19 v1(25.7,8.2)
PF7: CN9.26 CN11.11 U8.19 | length 107.6
  Top Layer w0.2: CN9.26@2.54,-17.78 v1(24.467,-17.78) ; v1(24.467,2.488) U8.19@24.467,4.39
  Signal Layer 2 w0.2: CN11.11@-7.62,33.02 -9.4,31.24 -9.4,9.239 -8.948,8.787 -8.948,3.348 -9.352,2.944 -9.352,-15.738 -8.535,-16.555 1.315,-16.555 CN9.26@2.54,-17.78
  Bottom Layer w0.127: 23.8,-5.9 23.354,-5.454 23.354,-2.25 24.467,-1.137
  Bottom Layer w0.2: 23.8,-5.9 23.8,-17.113 v1(24.467,-17.78) ; 24.467,-1.137 v1(24.467,2.488)
PF8: CN9.24 CN11.54 U8.20 | length 53.5
  Top Layer w0.2: CN11.54@-5.08,-20.32 -3.22,-20.32 -1.8,-18.9 -1.8,-17.04 -1.26,-16.5 1.28,-16.5 CN9.24@2.54,-15.24 v1(24.967,-15.24) ; v1(24.967,1.333) U8.20@24.967,4.415
  Bottom Layer w0.2: v1(24.967,-15.24) 24.5,-14.773 24.5,-5 24.22,-4.72 24.22,-1.88 24.967,-1.133 v1(24.967,1.333)
PF9: CN9.28 CN11.56 U8.21 | length 57.5
  Top Layer w0.2: CN11.56@-5.08,-22.86 -1.86,-22.86 -0.6,-21.6 1.26,-21.6 CN9.28@2.54,-20.32 v1(25.967,-20.32) ; v1(25.467,2.488) U8.21@25.467,4.39
  Bottom Layer w0.2: v1(25.467,2.488) 25.467,-2.658 24.9,-3.225 24.9,-14.533 25.467,-15.1 25.467,-19.82 v1(25.967,-20.32)
PF10: CN12.42 U8.22 | length 45.6
  Top Layer w0.2: v1(23.9,-5.2) 23.8,-5.2 22.7,-4.1 22.7,-1.6 25.967,1.667 U8.22@25.967,4.415 ; v1(52.5,-3.8) 54.575,-3.8 CN12.42@55.88,-5.105
  Signal Layer 2 w0.2: v1(23.9,-5.2) 25.6,-3.5 31,-3.5 32.2,-4.7 40.7,-4.7 41.6,-3.8 v1(52.5,-3.8)
PF11: CN12.62 U8.46 | length 86.8
  Top Layer w0.2: U8.46@35.042,10.99 39.41,10.99 39.7,10.7 v1(43.9,10.7)
  Signal Layer 2 w0.2: v1(31.148,-29.8) 51.4,-29.8 52,-29.2 54.575,-29.2 CN12.62@55.88,-30.505
  Signal Layer 3 w0.2: v1(31.148,-29.8) 31.6,-29.348 31.6,-22.239 31.148,-21.787 31.148,-21.413 31.6,-20.961 31.6,-5.1 32,-4.7 42.449,-4.7 43.3,-3.849 43.3,10.1 v1(43.9,10.7)
PF12: CN7.20 CN12.59 U8.47 | length 92.8
  Top Layer w0.2: v1(30.8,13.3) 32.829,11.271 33.771,11.271 33.99,11.49 U8.47@34.842,11.49 U8.47@35.042,11.49
  Signal Layer 2 w0.2: v1(31.6,20.3) 38.4,20.3 40.352,18.348 42.748,18.348 44.719,20.319 46.735,20.319 CN7.20@48.26,21.844 51.616,21.844 51.94,21.52 57.02,21.52 57.2,21.34 57.2,-26.4 56.9,-26.7 54.605,-26.7 CN12.59@53.34,-27.965
  Bottom Layer w0.2: v1(30.8,13.3) 30.8,18.3 31.6,19.1 v1(31.6,20.3)
PF13: CN10.2 CN12.57 U8.50 | length 77.3
  Top Layer w0.2: U8.50@35.042,12.99 v1(40.69,12.99) ; v1(40.69,16.09) 40.69,17.29 43,19.6 47.7,19.6 48.26,19.04 CN10.2@48.26,17.78 49.48,19 v1(56.6,19)
  Signal Layer 3 w0.2: CN12.57@53.34,-25.425 54.565,-24.2 56.47,-24.2 57.906,-22.764 57.906,-10.26 58.552,-9.614 58.552,17.048 v1(56.6,19)
  Bottom Layer w0.2: v1(40.69,12.99) v1(40.69,16.09)
PF14: CN10.8 CN12.50 U8.51 | length 55.7
  Top Layer w0.2: U8.51@35.067,13.49 v1(36.969,13.49) ; v1(37.5,8.9) 47,8.9 CN10.8@48.26,10.16 51.12,10.16 52.36,11.4 57.6,11.4 58.152,10.848 58.152,9.948 58.1,9.896 v1(58.1,7.7)
  Bottom Layer w0.2: v1(36.969,13.49) 37.525,12.934 37.525,8.925 v1(37.5,8.9) ; CN12.50@55.88,-15.265 57.2,-13.945 57.2,-9.5 58.152,-8.548 58.152,-6.213 58.1,-6.161 v1(58.1,7.7)
PF15: CN10.12 CN12.60 U8.52 | length 63.2
  Top Layer w0.2: U8.52@35.042,13.99 v1(38.124,13.99) ; v1(38,7.4) 42.1,7.4 43.105,6.395 46.945,6.395 CN10.12@48.26,5.08 ; v1(49.485,-29.2) 54.645,-29.2 CN12.60@55.88,-27.965
  Bottom Layer w0.2: v1(38,7.4) 38.4,7.8 38.4,13.714 v1(38.124,13.99) ; CN10.12@48.26,5.08 49.485,3.855 49.485,-2.447 49.9,-2.862 49.9,-17 49.485,-17.415 v1(49.485,-29.2)
PG0: CN9.29 CN11.59 U8.53 | length 91.1
  Top Layer w0.2: CN11.59@-7.62,-27.94 -6.36,-29.2 v1(-0.7,-29.2) 5.7,-29.2 8.9,-26 v1(29.5,-26) ; v1(32,13.5) 32.9,13.5 33.89,14.49 U8.53@34.842,14.49 U8.53@35.042,14.49
  Bottom Layer w0.2: v1(-0.7,-29.2) -0.7,-25.8 0,-25.1 CN9.29@0,-22.86 ; v1(29.5,-26) 29.5,-10.2 29.2,-9.9 29.2,-7.552 28.748,-7.1 28.748,-6.2 30.3,-4.648 30.3,-0.45 32.6,1.85 32.6,4.5 31.785,5.315 31.78,5.315 31.515,5.58 31.515,10.115 32,10.6 v1(32,13.5)
PG1: CN9.30 CN11.58 U8.54 | length 89.4
  Top Layer w0.2: CN11.58@-5.08,-25.4 -0.147,-25.4 2.393,-22.86 CN9.30@2.54,-22.86 v1(24.6,-22.86) ; U8.54@35.042,14.99 v1(38.124,14.99)
  Signal Layer 2 w0.2: v1(24.2,15.5) 24.7,16 29.848,16 31.7,14.148 33.148,14.148 33.99,14.99 v1(38.124,14.99)
  Bottom Layer w0.127: 23,-6.2 22.8,-6 22.8,-1.8 23.7,-0.9 23.7,3.333 25,4.633
  Bottom Layer w0.2: 23,-6.2 23,-21.26 v1(24.6,-22.86) ; v1(24.2,15.5) 24.2,12.228 25,11.428 25,4.633
PG2: CN11.42 U8.87 | length 67.1
  Top Layer w0.2: CN11.42@-5.08,-5.08 v1(-2.72,-5.08) ; U8.87@25.967,26.065 U8.87@25.967,25.865 25.967,24.933 28.6,22.3 v1(28.6,20.6)
  Signal Layer 2 w0.2: v1(-2.72,20.8) -1.885,21.635 4.765,21.635 5.1,21.3 9.6,21.3 10.6,20.3 16.15,20.3 16.45,20.6 v1(28.6,20.6)
  Bottom Layer w0.2: v1(-2.72,-5.08) v1(-2.72,20.8)
PG3: CN11.44 U8.88 | length 64.8
  Top Layer w0.2: CN11.44@-5.08,-7.62 -2.92,-7.62 -2.7,-7.4 v1(-2.7,-6.5) ; v1(25.248,18.2) 25.248,24.748 25.467,24.967 U8.88@25.467,25.865 U8.88@25.467,26.065
  Signal Layer 2 w0.2: v1(-2.2,19) -2.195,19.005 3.395,19.005 4.2,18.2 v1(25.248,18.2)
  Bottom Layer w0.2: v1(-2.7,-6.5) -2.2,-6 v1(-2.2,19)
PG4: CN12.69 U8.89 | length 96.9
  Top Layer w0.2: U8.89@24.967,26.065 U8.89@24.967,25.865 24.967,25.067 24.9,25 24.9,22.1 23.8,21 23.8,16.6 v1(25.254,15.146)
  Signal Layer 2 w0.2: v1(28.5,-40.665) CN12.69@53.34,-40.665
  Bottom Layer w0.127: 23.4,-6.1 23.1,-5.8 23.1,-2.006 24,-1.106 24,3 25.5,4.5
  Bottom Layer w0.2: 23.4,-6.1 23.4,-19.1 26,-21.7 26,-34.3 28.5,-36.8 v1(28.5,-40.665) ; v1(25.254,15.146) 24.9,14.792 24.9,12.6 26.3,11.2 26.3,8.1 25.5,7.3 25.5,4.5
PG5: CN12.68 U8.90 | length 96.6
  Top Layer w0.2: v1(23.3,15.6) 23.3,21.513 23.748,21.961 23.748,22.387 24.467,23.106 U8.90@24.467,25.865 U8.90@24.467,26.065
  Signal Layer 2 w0.2: v1(28,-37.5) 31,-37.5 31.2,-37.7 45.761,-37.7 45.961,-37.5 46.651,-36.81 54.565,-36.81 CN12.68@55.88,-38.125
  Bottom Layer w0.127: 22.5,-6.3 22.5,-1.6 23.4,-0.7 23.4,3.7 24.6,4.9
  Bottom Layer w0.2: 22.5,-6.3 22.6,-6.4 22.6,-21.6 25.3,-24.3 25.3,-34.4 28,-37.1 v1(28,-37.5) ; v1(23.3,15.6) 23.8,15.1 23.8,12 24.6,11.2 24.6,4.9
PG6: CN12.70 U8.91 | length 100.1
  Top Layer w0.2: v1(22.8,16.4) 22.8,22.2 23.967,23.367 U8.91@23.967,25.865 U8.91@23.967,26.065
  Signal Layer 2 w0.2: v1(27.5,-40.1) 30.1,-40.1 31.5,-38.7 35.8,-38.7 36.5,-39.4 54.615,-39.4 CN12.70@55.88,-40.665
  Bottom Layer w0.127: 22.2,-6.7 22.2,-1.5 23.1,-0.6 23.1,4.2 24.248,5.348
  Bottom Layer w0.2: 22.2,-6.7 22.2,-21.8 24.8,-24.4 24.8,-35.6 27.5,-38.3 v1(27.5,-40.1) ; v1(22.8,16.4) 22.8,15.2 23.473,14.527 23.473,11.627 24.248,10.852 24.248,5.348
PG7: SB127.2 SB128.2 SB168.1 U8.92 | length 96.9
  Top Layer w0.2: v1(20.8,15.4) 20.8,20.9 23.467,23.567 U8.92@23.467,25.865 v1(23.467,29.147)
  Signal Layer 2 w0.2: v1(24.9,-38.1) v1(46,-38.1)
  Bottom Layer w0.2: v1(20.8,15.4) 22.352,13.848 22.352,5.852 21.967,5.467 21.967,0.867 20.9,-0.2 20.9,-22.8 23,-24.9 23,-36.2 v1(24.9,-38.1) ; v1(23.467,29.147) 23.85,29.53 SB128.2@23.85,30.6 SB127.2@25.35,30.6 ; v1(46,-38.1) SB168.1@47.4,-38.1
PG8: SB129.2 SB130.2 SB167.2 U8.93 | length 98.6
  Top Layer w0.2: v1(20.9,13.2) 20.9,14.661 20.348,15.213 20.348,15.587 20.473,15.712 20.473,21.292 22.967,23.786 U8.93@22.967,25.865 U8.93@22.967,26.065 ; U8.93@22.967,26.09 v1(22.967,27.992)
  Signal Layer 2 w0.2: v1(19.4,-36.2) 31.9,-36.2 32.3,-36.6 v1(45.9,-36.6)
  Bottom Layer w0.2: v1(19.4,-36.2) 19.4,-0.5 20.967,1.067 20.967,2.7 21.027,2.76 21.027,13.073 v1(20.9,13.2) ; SB130.2@20.85,30.6 SB129.2@22.35,30.6 22.35,28.609 v1(22.967,27.992) ; v1(45.9,-36.6) SB167.2@47.3,-36.6
PG9: CN11.63 U8.124 | length 73.4
  Top Layer w0.2: CN11.63@-7.62,-33.02 -6.34,-34.3 3.5,-34.3 v1(10.9,-26.9) ; v1(10.31,16.49) U8.124@13.392,16.49
  Bottom Layer w0.2: v1(10.31,16.49) 12.717,16.49 14.1,15.107 14.1,8.8 12.827,7.527 12.827,3.827 10.3,1.3 10.3,-9 10.9,-9.6 v1(10.9,-26.9)
PG10: CN11.66 U8.125 | length 68.1
  Top Layer w0.2: CN11.66@-5.08,-35.56 3.14,-35.56 v1(10.4,-28.3) ; v1(11.465,15.99) U8.125@13.367,15.99
  Bottom Layer w0.2: v1(10.4,-28.3) 10.4,-9.9 9.7,-9.2 9.7,1.4 12.3,4 12.3,7.6 13.7,9 13.7,14.69 12.4,15.99 v1(11.465,15.99)
PG12: CN11.65 U8.126 | length 73.5
  Top Layer w0.2: CN11.65@-7.62,-35.56 -6.38,-36.8 2.8,-36.8 v1(9.9,-29.7) ; v1(10.31,15.49) U8.126@13.392,15.49
  Bottom Layer w0.2: v1(9.9,-29.7) 9.9,-10.16 9.2,-9.46 9.2,1.7 11.8,4.3 11.8,7.7 13.3,9.2 13.3,14.2 12.01,15.49 v1(10.31,15.49)
PG13: CN11.68 U8.127 | length 68.2
  Top Layer w0.2: CN11.68@-5.08,-38.1 2.4,-38.1 v1(9.4,-31.1) ; v1(11.465,14.99) U8.127@13.367,14.99
  Bottom Layer w0.2: v1(9.4,-31.1) 9.4,-10.4 8.7,-9.7 8.7,1.9 11.3,4.5 11.3,7.8 12.9,9.4 12.9,13.89 11.8,14.99 v1(11.465,14.99)
PG14: CN12.61 U8.128 | length 98.3
  Top Layer w0.2: v1(10.31,14.49) U8.128@13.392,14.49 ; v1(10.6,-32.1) 51.745,-32.1 CN12.61@53.34,-30.505
  Bottom Layer w0.2: v1(10.31,14.49) 11.61,14.49 12.5,13.6 12.5,9.6 10.8,7.9 10.8,4.7 8.1,2 8.1,-9.9 8.9,-10.7 8.9,-31.6 9.4,-32.1 v1(10.6,-32.1)
PG15: CN11.64 U8.131 | length 60.8
  Top Layer w0.2: CN11.64@-5.08,-33.02 3.78,-33.02 v1(7.9,-28.9) ; v1(11.465,12.99) U8.131@13.367,12.99
  Bottom Layer w0.2: v1(7.9,-28.9) 7.9,-10.5 6.9,-9.5 6.9,2.255 9.8,5.155 9.8,8.1 11,9.3 11,12.525 v1(11.465,12.99)
PH0: CN11.29 SB142.2 | length 39.8
  Signal Layer 2 w0.2: CN11.29@-7.62,10.16 -6.305,11.475 -4.025,11.475 -1.5,14 4.8,14 7.3,11.5 13.9,11.5 14.9,10.5 v1(26.8,10.5)
  Bottom Layer w0.2: v1(26.8,10.5) 27.2,10.1 SB142.2@27.2,8.3
PH0-OSC_IN: SB6.1 SB142.1 SB143.1 U8.23 | length 11.9
  Top Layer w0.2: 25.9,-0.3 25.9,0.151 26.467,0.717 v1(26.467,2.488) U8.23@26.467,4.39
  Bottom Layer w0.2: v1(26.467,2.488) 27.2,3.221 SB142.1@27.2,7.2 SB143.1@28.7,7.2 29,6.9
PH1: CN11.31 SB145.2 | length 37.4
  Signal Layer 2 w0.2: CN11.31@-7.62,7.62 -6.305,8.935 4.865,8.935 6.5,7.3 v1(26.3,7.3)
  Bottom Layer w0.2: v1(26.3,7.3) 26.3,5.132 SB145.2@26.332,5.1
PH1-OSC_OUT: SB7.1 SB145.1 U8.24 | length 8.3
  Top Layer w0.2: U8.24@26.967,4.415 v1(26.967,1.333) 26.967,0.633 27.409,0.191 SB7.1@27.409,-0.085
  Bottom Layer w0.2: SB145.1@26.332,4 25.967,3.635 25.967,1.633 26.267,1.333 v1(26.967,1.333)
PH3-BOOT0: CN11.7 R33.1 U8.137 | length 55
  Top Layer w0.2: v1(-10,11.475) -4.573,11.475 -1.048,15 4.7,15 8.9,10.8 R33.1@8.9,10 8.91,9.99 U8.137@13.367,9.99
  Bottom Layer w0.2: v1(-10,11.475) -10,35.72 CN11.7@-7.62,38.1
PWR_ENN: R23.2 U2.28 U4.4 | length 35.1
  Top Layer w0.127: U2.28@28.38,60.98 29.289,60.98 29.82,60.449 29.82,58.711 34.428,54.102 41.466,54.102 ; v1(47.1,54) 41.574,54 41.571,53.997 41.466,54.102 ; U4.4@50.225,58.2 44,58.2 41.466,55.666 41.466,54.102
  Top Layer w0.254: R23.2@46.925,55 47.012,54.912 47.1,54.825 v1(47.1,54)
STLINK_USB_D_N: CN1.2 U1.1 U1.6 U2.32 | length 20.2
  Top Layer w0.155: U2.32@28.38,62.98 28.975,62.98 29.034,63.039 32.05,63.039 32.208,63.04 32.608,63.44 32.831,63.663 32.831,63.82 32.831,64.808 33.498,65.475 38.204,65.475 38.621,65.892 38.621,66.344 39.38,67.103 U1.6@39.38,67.793 U1.1@39.38,70.093 39.38,70.786 38.621,71.545 38.621,72.384 38.75,72.513 38.75,73.218 CN1.2@38.75,73.279
STLINK_USB_D_P: CN1.3 R8.2 U1.3 U1.4 U2.33 | length 21.2
  Top Layer w0.155: U2.33@28.38,63.48 28.975,63.48 29.034,63.42 32.05,63.42 32.45,63.82 32.45,64.966 33.34,65.856 38.046,65.856 38.24,66.05 38.24,66.343 37.48,67.103 U1.4@37.48,67.736 ; R8.2@35.839,67.729 37.474,67.729 U1.4@37.48,67.736 ; CN1.3@38.1,73.279 38.1,73.218 38.1,72.513 38.24,72.373 38.24,71.546 37.48,70.786 U1.3@37.48,70.093 U1.4@37.48,67.793 U1.4@37.48,67.736
STLK_OSC_IN: C4.1 U2.5 X1.1 | length 6.6
  Top Layer w0.127: C4.1@13.582,63.703 X1.1@16.292,63.703 ; X1.1@16.307,63.688 16.906,63.688 17.614,62.98 U2.5@19.88,62.98
STLK_OSC_OUT: C5.1 U2.6 X1.2 | length 6.6
  Top Layer w0.127: C5.1@13.582,61.773 X1.2@16.292,61.773 ; X1.2@16.307,61.788 16.906,61.788 17.598,62.48 U2.6@19.88,62.48 U2.6@19.876,62.484
STLK_RST: C2.2 JP2.2 U2.7 | length 56.8
  Top Layer w0.127: U2.7@19.88,61.979 20.585,61.979 21.88,63.274 21.88,64.364 v1(20.625,65.619) ; v1(20.625,67.132) 21.029,67.537 22.662,67.537 22.885,67.76 C2.2@22.885,68.286
  Signal Layer 2 w0.127: JP2.2@-7.62,58.42 -7.62,66.37 1.321,75.311 18.471,75.311 20.625,73.157 v1(20.625,67.132) v1(20.625,65.619)
STM_JTCK: SB102.2 U2.37 | length 37.5
  Top Layer w0.127: v1(14.772,71.095) 14.645,71.221 14.645,74.215 16.3,75.87 31.547,75.87 32.766,74.651 32.766,67.234 31.648,66.116 26.924,66.116 26.88,66.16 U2.37@26.88,66.48
  Bottom Layer w0.127: SB102.2@13.8,71.12 v1@14.746,71.12
STM_JTMS: SB106.2 U2.34 | length 20.1
  Top Layer w0.127: v1(24.79,63.957) 28.357,63.957 U2.34@28.38,63.98
  Bottom Layer w0.127: SB106.2@13.8,66.04 18.186,66.04 20.269,63.957 ; v1(24.79,63.957) 20.269,63.957 ; v1@24.882,63.947 24.79,63.947 24.78,63.947 24.752,63.919 20.307,63.919 20.269,63.957
SWO: SB108.2 SB140.1 U100.6 | length 63.7
  Bottom Layer w0.2: 7.5,12.5 7.85,12.15 8,12 SB140.1@8,12.3 8,18.1 8.3,18.4 10.8,18.4 12.9,20.5 12.9,38.65 13.95,39.7 13.95,50.25 15.2,51.5 27.966,51.5 28.876,52.41 U100.6@28.876,54.635 28.876,55.385 29.066,55.575 30.429,55.575 30.734,55.27
T_JTCK: R15.2 SB101.1 U2.15 U2.26 | length 47.6
  Top Layer w0.127: R15.2@2.07,66.04 2.826,66.04 3.613,66.827 v1(3.613,72.415) ; U2.15@22.38,57.98 22.38,60.074 22.835,60.528 22.835,60.554 ; v1(22.835,64.897) 22.835,60.554 ; U2.26@28.38,59.98 28.38,59.972 27.231,59.972 27.223,59.98 23.408,59.98 22.835,60.554
  Bottom Layer w0.127: 3.613,73.66 v1(3.613,72.415) 21.59,72.415 22.301,71.704 22.301,66.7 ; 22.327,66.7 22.835,66.192 v1(22.835,64.897)
T_JTMS: R16.2 R24.2 SB105.1 U2.27 U100.7 | length 43.5
  Top Layer w0.127: R16.2@2.07,64.541 v1(3.073,64.541) ; v1@27.438,60.477 v1(27.441,60.48) U2.27@28.38,60.48 28.979,60.48 29.235,60.223 29.235,58.623 30.556,57.302 30.556,54.901 30.328,54.674 29.616,54.674 28.613,54.674 28.372,54.915 v1(28.372,55.778)
  Signal Layer 2 w0.127: v1@3.048,64.567 v1(3.048,67.183)
  Bottom Layer w0.127: v1(3.048,67.183) 3.048,68.015 3.613,68.58 ; v1(3.073,64.541) 7.544,64.541 11.605,60.48 v1(27.441,60.48) ; v1(28.372,55.778) 28.376,55.774 U100.7@28.376,54.635
T_MCO: R19.1 U2.29 | length 2.3
  Top Layer w0.127: U2.29@28.38,61.479 R19.1@30.685,61.479
T_NRST: JP3.1 R17.2 U2.18 | length 31.6
  Top Layer w0.127: R17.2@2.07,63.043 3.81,63.043 4.191,62.662 4.191,61.138 2.54,59.487 JP3.1@2.54,58.419 ; v1(23.876,56.49) 23.88,56.494 U2.18@23.88,57.98
  Bottom Layer w0.127: JP3.1@2.54,58.419 JP3.1@2.54,58.419 2.54,58.275 5.035,58.275 5.905,57.405 ; 5.9,57.4 6.2,57.1 12.6,57.1 13.281,57.781 22.584,57.781 v1(23.876,56.49) v1@23.8,56.49
T_SWDIO_IN: R24.1 U2.25 U100.2 | length 4.7
  Top Layer w0.127: U2.25@28.38,59.48 v1(28.38,58.699) 29.616,57.462 R24.1@29.616,56.274
  Bottom Layer w0.127: U100.2@28.376,57.735 28.376,58.694 v1(28.38,58.699)
T_SWO: R18.2 SB108.1 U2.31 U100.3 | length 38.3
  Top Layer w0.127: R18.2@2.07,61.544 v1(3.073,61.544) ; U2.31@28.38,62.48 v1(29.57,62.48)
  Bottom Layer w0.127: v1(3.073,61.544) 9.5,61.544 12.929,58.115 22.987,58.115 25.102,56 27.751,56 28.876,57.125 ; v1(29.57,62.48) 29.57,59.973 28.888,59.292 28.888,57.747 U100.3@28.876,57.735 28.876,57.125 ; 30.734,56.985 29.015,56.985 28.876,57.125
T_VCP_RX: CN6.1 SB126.2 SB129.1 U2.12 | length 57
  Top Layer w0.2: CN6.1@10.16,58.42 12.538,58.42 14.9,56.058 18.567,56.058 v1(19.875,57.366) 19.88,57.37 U2.12@19.88,59.48 ; v1(22.35,33.6) v1(28.148,33.6)
  Signal Layer 2 w0.2: v1(19.875,57.366) 20.599,58.09 27.911,58.09 28.876,57.125 28.876,47.076 28.4,46.6 v1(28.4,45.1)
  Bottom Layer w0.2: SB129.1@22.35,31.7 v1(22.35,33.6) ; SB126.2@28.15,31.8 28.148,31.802 v1(28.148,33.6) 28.148,34.6 27.348,35.4 27.348,43.768 28.4,44.82 v1(28.4,45.1)
T_VCP_TX: CN6.2 SB124.2 SB127.1 U2.13 | length 58.9
  Top Layer w0.2: CN6.2@10.16,55.88 12.22,55.88 13.084,55.016 19.443,55.016 v1(21.38,56.954) U2.13@21.38,57.98 ; v1(25.35,34.15) 28.75,34.15 29.45,33.45 v1(31.15,33.45)
  Signal Layer 2 w0.2: v1(21.38,56.954) 21.424,56.998 26.187,56.998 26.893,56.292 26.893,55.473 28.066,54.3 28.066,47.466 27.948,47.348 27.948,44.052 29.197,42.803 29.197,40.1 29.927,39.37 30.667,39.37 31.237,38.8 31.237,35.637 29.75,34.15 v1(25.35,34.15)
  Bottom Layer w0.2: SB127.1@25.35,31.7 v1(25.35,34.15) ; SB124.2@31.15,31.8 v1(31.15,33.45)
UCPD_CC1_C: CN15.A5 SB10.2 U11.7 | length 21.8
  Top Layer w0.2: SB10.2@20.2,-40.2 v1(20.2,-38.9) ; U11.7@26.525,-43.5 27.3,-43.5 v1(27.7,-43.9) 28.8,-43.9 29.2,-43.5 32.6,-43.5 33.65,-44.55 CN15.A5@33.65,-45.32
  Bottom Layer w0.2: v1(20.2,-38.9) 20.2,-42.1 22.5,-44.4 27.2,-44.4 v1(27.7,-43.9)
UCPD_CC2_C: CN15.B5 SB11.2 U11.9 | length 22.9
  Top Layer w0.2: SB11.2@21.7,-40.2 v1(21.7,-38.9) ; U11.9@26.525,-42.5 27.3,-42.5 v1(27.7,-42.1)
  Bottom Layer w0.2: v1(21.7,-38.9) 21.7,-39.5 23.85,-41.65 26.15,-41.65 26.6,-42.1 v1(27.7,-42.1) 29.1,-42.1 30.975,-43.975 30.975,-47.092 31.375,-47.492 31.375,-47.875 31.8,-48.3 34.18,-48.3 CN15.B5@35.2,-47.28
USB_FS_N: CN15.A7 CN15.B7 SB137.2 U8.103 U9.1 U9.6 | length 92.2
  Top Layer w0.155: U8.103@17.967,26.065 U8.103@17.967,25.865 17.967,25.162 17.907,25.103 17.907,20.193 18,20.1 v1(18.5,20.1) ; CN15.B7@34,-46.57 34,-46.509 34.65,-45.859 CN15.A7@34.65,-45.32 34.65,-43.6 35.35,-42.9 U9.6@35.35,-42.65 U9.1@35.35,-40.35 35.2,-40.2 35.2,-39.5 v1(34.9,-39.2)
  Bottom Layer w0.155: SB137.2@18.5,21.1 v1(18.5,20.1) 18,20.1 17.9,20 17.9,19.446 23.1,14.246 23.1,5.261 22.739,4.9 22.739,0.3 21.7,-0.739 21.7,-21.961 24.081,-24.342 24.081,-35.881 27,-38.8 27,-40.7 27.5,-41.2 29.142,-41.2 32.423,-37.919 34.115,-37.919 34.59,-38.395 34.59,-38.891 v1(34.9,-39.2)
USB_FS_P: CN15.A6 CN15.B6 SB138.2 U8.104 U9.3 U9.4 | length 93
  Top Layer w0.155: v1(17,20.1) 17.4,20.1 17.526,20.226 17.526,25.103 17.467,25.162 U8.104@17.467,25.865 U8.104@17.467,26.065 ; v1(33.9,-39.2) 33.6,-39.5 33.6,-40.2 U9.3@33.45,-40.35 U9.4@33.45,-42.65 33.45,-43 34.15,-43.7 v1(34.15,-44.3) CN15.A6@34.15,-45.32
  Bottom Layer w0.155: SB138.2@17,21.1 v1(17,20.1) 17.4,20.1 17.519,19.981 17.519,19.288 22.719,14.088 22.719,5.419 22.358,5.058 22.358,0.458 21.319,-0.581 21.319,-22.119 23.7,-24.5 23.7,-36.039 26.619,-38.958 26.619,-40.858 27.342,-41.581 29.3,-41.581 32.581,-38.3 33.957,-38.3 34.209,-38.553 34.209,-38.891 v1(33.9,-39.2) ; v1(34.15,-44.3) 34.8,-44.95 CN15.B6@34.8,-46.57
USB_RENUMN: R10.2 U2.38 | length 19.6
  Top Layer w0.127: U2.38@26.38,66.48 26.38,67.122 26.594,67.335 v1(31.49,67.335) ; v1(43.122,64.338) R10.2@43.122,65.265
  Bottom Layer w0.127: v1(31.49,67.335) 40.124,67.335 v1(43.122,64.338)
